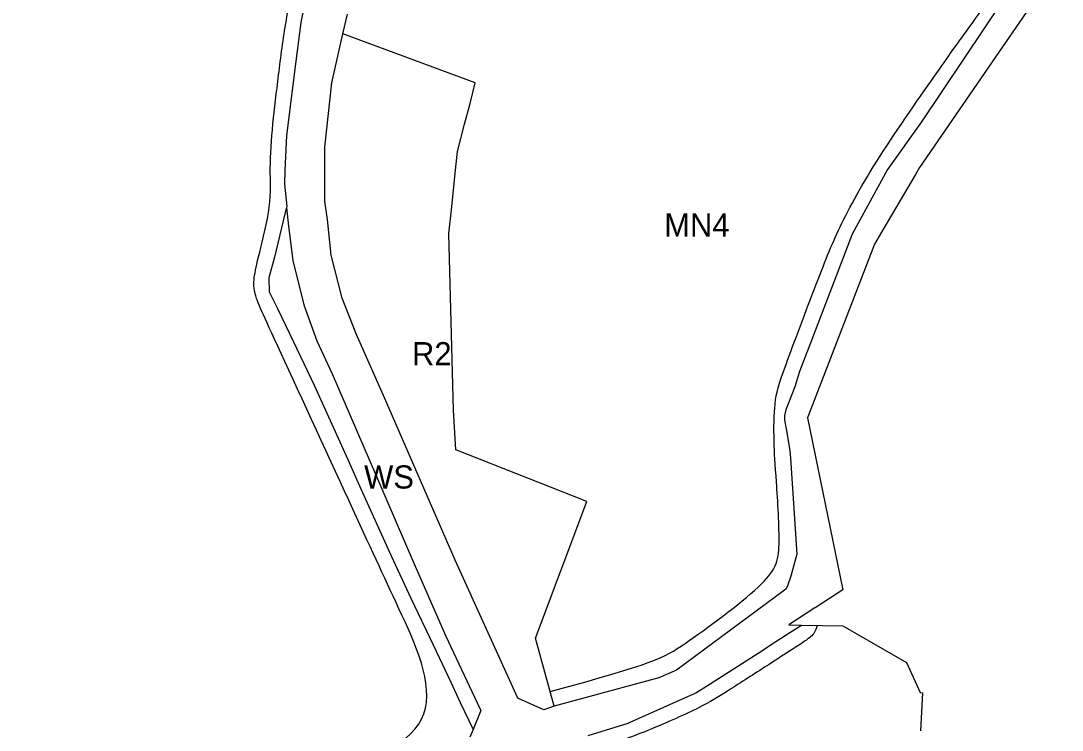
# Model space of a CAD drawing. Extents: x 7413438 to 7416393, y 5541665 to 5544118.
# Drawn here: x 7415261.6 to 7415531.4, y 5542815.6 to 5542999.4 of the extents above; entities that cross this region are included whole.
import ezdxf

# ---------------------------------------------------------------- set-up
doc = ezdxf.new("R2010")
doc.units = 0
for name, color, linetype in [('linie_rozgraniczajace', 7, 'Continuous'), ('linie_zabudowy_nieprzekraczalne', 7, 'Continuous'), ('oznaczenia_przeznaczen', 7, 'Continuous')]:
    doc.layers.add(name, color=color, linetype=linetype)

msp = doc.modelspace()

# ---------------------------------------------------------------- linework, layer by layer
at = {"layer": 'linie_rozgraniczajace'}
for p, q in [((7415526.08, 5543019.69), (7415495.03, 5542973.19)), ((7415531.45, 5543015.17), (7415515.94, 5542992.61)), ((7415335.89, 5543007.91), (7415334.12, 5542998.99)), ((7415345.05, 5542996.02), (7415346.21, 5543001.13)), ((7415334.12, 5542998.99), (7415332.88, 5542988.9)), ((7415342.17, 5542983.31), (7415345.05, 5542996.02)), ((7415379.36, 5542983.28), (7415345.05, 5542996.02)), ((7415515.94, 5542992.61), (7415494.51, 5542961.42)), ((7415515.94, 5542992.61), (7415515.94, 5542992.61)), ((7415332.88, 5542988.9), (7415330.46, 5542969.7)), ((7415340.33, 5542966.66), (7415342.17, 5542983.31)), ((7415377.98, 5542977.93), (7415379.36, 5542983.28)), ((7415379.36, 5542983.28), (7415379.36, 5542983.28)), ((7415376.59, 5542972.57), (7415377.98, 5542977.93)), ((7415495.03, 5542973.19), (7415486.17, 5542960.9)), ((7415374.76, 5542965.49), (7415376.59, 5542972.57)), ((7415330.46, 5542969.7), (7415329.98, 5542960.58)), ((7415340.4, 5542952.61), (7415340.33, 5542966.66)), ((7415374.16, 5542959.9), (7415374.76, 5542965.49)), ((7415329.98, 5542960.58), (7415329.91, 5542957.05)), ((7415373.23, 5542951.17), (7415374.16, 5542959.9)), ((7415486.17, 5542960.9), (7415477.03, 5542944.07)), ((7415493.42, 5542959.57), (7415485.25, 5542945.65)), ((7415494.51, 5542961.42), (7415493.42, 5542959.57)), ((7415329.91, 5542957.05), (7415330.53, 5542951.27)), ((7415330.53, 5542951.27), (7415330.45, 5542950.96)), ((7415341.09, 5542947.87), (7415340.4, 5542952.61)), ((7415372.5, 5542944.25), (7415373.23, 5542951.17)), ((7415330.03, 5542949.35), (7415327.28, 5542938.17)), ((7415330.45, 5542950.96), (7415330.03, 5542949.35)), ((7415330.45, 5542950.96), (7415330.95, 5542946.2)), ((7415330.95, 5542946.2), (7415332.07, 5542937.29)), ((7415341.97, 5542938.7), (7415341.09, 5542947.87)), ((7415485.25, 5542945.65), (7415482.81, 5542941.5)), ((7415373.74, 5542898.52), (7415372.5, 5542944.25)), ((7415477.03, 5542944.07), (7415465.84, 5542914.99)), ((7415482.81, 5542941.5), (7415465.73, 5542897.2)), ((7415327.28, 5542938.17), (7415325.88, 5542932.78)), ((7415344.85, 5542927.52), (7415341.97, 5542938.7)), ((7415332.07, 5542937.29), (7415334.88, 5542925.77)), ((7415325.88, 5542932.78), (7415325.97, 5542929.13)), ((7415325.97, 5542929.13), (7415328.05, 5542924.83)), ((7415348.49, 5542918.29), (7415344.85, 5542927.52)), ((7415328.05, 5542924.83), (7415332.24, 5542916.21)), ((7415334.88, 5542925.77), (7415338.27, 5542916.46)), ((7415332.24, 5542916.21), (7415337.6, 5542904.94)), ((7415338.27, 5542916.46), (7415342.3, 5542907.92)), ((7415355.58, 5542902.26), (7415348.49, 5542918.29)), ((7415465.84, 5542914.99), (7415463.39, 5542908.52)), ((7415342.3, 5542907.92), (7415353.48, 5542881.93)), ((7415463.39, 5542908.52), (7415462.14, 5542904.57)), ((7415337.6, 5542904.94), (7415346.35, 5542885.71)), ((7415462.14, 5542904.57), (7415459.84, 5542898.61)), ((7415374.13, 5542859.59), (7415355.58, 5542902.26)), ((7415374.28, 5542888.19), (7415373.74, 5542898.52)), ((7415459.84, 5542898.61), (7415459.5, 5542897.08)), ((7415459.5, 5542897.08), (7415459.51, 5542895.9)), ((7415465.73, 5542897.2), (7415465.47, 5542896.54)), ((7415459.51, 5542895.9), (7415459.93, 5542893.69)), ((7415465.47, 5542896.54), (7415474.61, 5542851.95)), ((7415459.93, 5542893.69), (7415460.88, 5542888.03)), ((7415408.23, 5542874.78), (7415374.28, 5542888.19)), ((7415460.88, 5542888.03), (7415461.01, 5542886.08)), ((7415346.35, 5542885.71), (7415349.71, 5542878.07)), ((7415461.01, 5542886.08), (7415462.67, 5542861.16)), ((7415353.48, 5542881.93), (7415363.45, 5542858.82)), ((7415349.71, 5542878.07), (7415357.52, 5542860.72)), ((7415394.91, 5542839.37), (7415408.23, 5542874.78)), ((7415357.52, 5542860.72), (7415362.68, 5542849.81)), ((7415390.37, 5542823.84), (7415374.13, 5542859.59)), ((7415462.67, 5542861.16), (7415461.13, 5542855.48)), ((7415363.45, 5542858.82), (7415371.75, 5542839.91)), ((7415461.13, 5542855.48), (7415460.26, 5542852.94)), ((7415459.51, 5542851.84), (7415431.46, 5542831.14)), ((7415459.91, 5542852.22), (7415459.51, 5542851.84)), ((7415460.26, 5542852.94), (7415459.91, 5542852.22)), ((7415474.61, 5542851.95), (7415467.46, 5542847.29)), ((7415362.68, 5542849.81), (7415368.39, 5542837.72)), ((7415467.38, 5542847.23), (7415460.62, 5542842.83)), ((7415467.46, 5542847.29), (7415467.38, 5542847.23)), ((7415457.25, 5542838.52), (7415460.89, 5542840.86)), ((7415460.62, 5542842.83), (7415463.9, 5542842.78)), ((7415460.89, 5542840.86), (7415461.6, 5542841.31)), ((7415461.6, 5542841.31), (7415463.9, 5542842.78)), ((7415463.9, 5542842.78), (7415474.57, 5542842.61)), ((7415474.57, 5542842.61), (7415491.14, 5542833.09)), ((7415368.39, 5542837.72), (7415372.97, 5542827.96)), ((7415371.75, 5542839.91), (7415379.17, 5542824.12)), ((7415399.83, 5542821.77), (7415394.91, 5542839.37)), ((7415452.62, 5542835.55), (7415457.25, 5542838.52)), ((7415439.23, 5542826.95), (7415452.62, 5542835.55)), ((7415491.14, 5542833.09), (7415494.65, 5542825.36)), ((7415431.46, 5542831.14), (7415426.94, 5542829.11)), ((7415372.97, 5542827.96), (7415375.47, 5542822.74)), ((7415420.54, 5542827.38), (7415399.83, 5542821.77)), ((7415426.94, 5542829.11), (7415420.54, 5542827.38)), ((7415436.8, 5542825.39), (7415439.23, 5542826.95)), ((7415419.5, 5542817.61), (7415436.14, 5542825.04)), ((7415436.14, 5542825.04), (7415436.2, 5542825.06)), ((7415436.2, 5542825.06), (7415436.5, 5542825.21)), ((7415436.5, 5542825.21), (7415436.78, 5542825.38)), ((7415436.78, 5542825.38), (7415436.8, 5542825.39)), ((7415494.65, 5542825.36), (7415495.27, 5542825.28)), ((7415495.27, 5542825.28), (7415494.71, 5542815.37)), ((7415375.47, 5542822.74), (7415375.44, 5542822.74)), ((7415375.44, 5542822.74), (7415378.77, 5542815.75)), ((7415379.17, 5542824.12), (7415379.13, 5542824.1)), ((7415379.13, 5542824.1), (7415380.76, 5542820.63)), ((7415390.54, 5542823.75), (7415390.37, 5542823.84)), ((7415397.09, 5542820.83), (7415390.54, 5542823.75)), ((7415399.83, 5542821.77), (7415397.09, 5542820.83)), ((7415380.76, 5542820.63), (7415378.77, 5542815.75)), ((7415408.58, 5542814.17), (7415418.95, 5542817.4)), ((7415418.95, 5542817.4), (7415419.26, 5542817.51)), ((7415419.26, 5542817.51), (7415419.5, 5542817.61)), ((7415378.77, 5542815.75), (7415377.96, 5542813.77))]:
    msp.add_line(p, q, dxfattribs=at)
at = {"layer": 'linie_zabudowy_nieprzekraczalne'}
for points in [[(7415224.24, 5542764.93), (7415234.87, 5542768.93), (7415252.45, 5542775.15), (7415267.62, 5542778.59), (7415300.4, 5542786.16), (7415306.31, 5542787.89), (7415321.64, 5542794.04), (7415341.99, 5542803.09), (7415373.83, 5542816.66), (7415358.63, 5542848.96), (7415349.07, 5542869.68), (7415324.44, 5542923.07), (7415321.98, 5542928.69), (7415321.86, 5542932.66), (7415323.07, 5542937.93), (7415326.67, 5542952.06), (7415325.97, 5542960.66), (7415326.79, 5542972.64), (7415328.33, 5542984.95), (7415330.18, 5542999.75), (7415333.24, 5543013.48), (7415339.07, 5543034.4), (7415348.26, 5543068.35), (7415353.84, 5543088.85), (7415355.35, 5543096.84)], [(7415398.75, 5542825.57), (7415425.57, 5542832.86), (7415430.65, 5542835.5), (7415456.62, 5542854.66), (7415458.62, 5542861.54), (7415457.28, 5542881.79), (7415456.66, 5542890.14), (7415456.81, 5542901), (7415458.48, 5542906.91), (7415468.57, 5542933.52), (7415473.53, 5542946.04), (7415483.62, 5542964.23), (7415502.34, 5542990.63), (7415505, 5542994.59), (7415510.05, 5543001.09), (7415518.09, 5543014.38), (7415521.57, 5543018.72), (7415527.6, 5543028.87)], [(7415467.94, 5542842.69), (7415467.54, 5542841.13), (7415466.64, 5542839.86), (7415463.04, 5542837.46), (7415454.77, 5542832.15), (7415443.68, 5542825.04), (7415438.79, 5542821.9), (7415424.47, 5542815.43), (7415413.85, 5542811.6), (7415404.29, 5542808.46)]]:
    msp.add_open_spline(points, degree=3, dxfattribs=at)

# ---------------------------------------------------------------- texts
at = {"layer": 'oznaczenia_przeznaczen'}
for s, p in [('MN4', (7415428.3, 5542943.47)), ('R2', (7415362.95, 5542910.12)), ('WS', (7415350.53, 5542878.18))]:
    msp.add_text(s, height=6, dxfattribs=at).set_placement(p)

doc.saveas('drawing.dxf')
